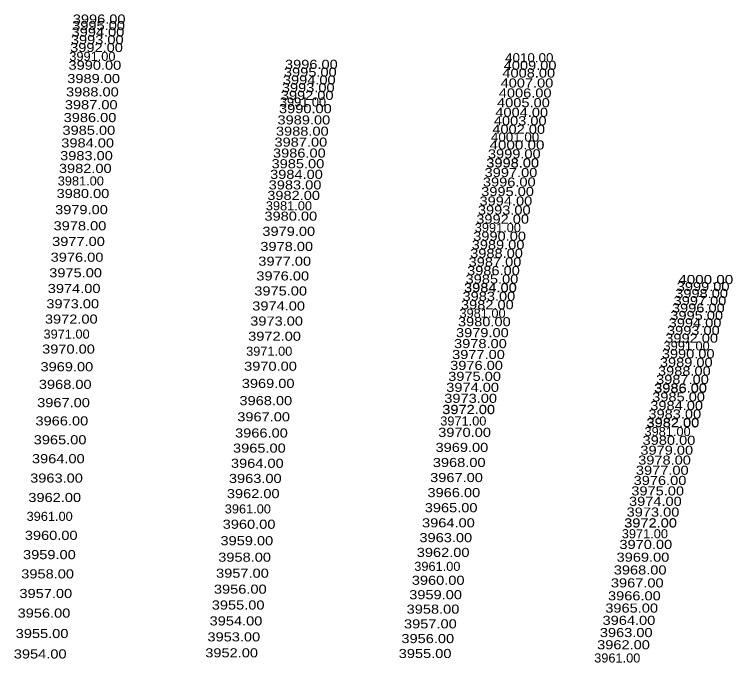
# Model space of a CAD drawing. Extents: x 49942 to 56479, y 47140 to 53283.
# Drawn here: x 54100.5 to 54495.6, y 49903.4 to 50259.9 of the extents above; entities that cross this region are included whole.
import ezdxf

# ---------------------------------------------------------------- set-up
doc = ezdxf.new("R2010")
doc.units = 0
doc.header["$LTSCALE"] = 2
doc.layers.add('29', color=7, linetype='Continuous')

msp = doc.modelspace()

# ---------------------------------------------------------------- texts
at = {"layer": '29'}
for s, width, p in [('3996.00', 1.2, (54132.674, 50254.795)), ('3995.00', 1.2, (54132.343, 50251.232)), ('3994.00', 1.2, (54132.012, 50247.668)), ('3993.00', 1.2, (54131.616, 50243.411)), ('3992.00', 1.2, (54131.22, 50239.153)), ('3991.00', 1.05, (54130.768, 50234.287)), ('4010.00', 1.1, (54370.453, 50233.532)), ('3990.00', 1.2, (54130.316, 50229.421)), ('3996.00', 1.2, (54249.399, 50229.894)), ('4009.00', 1.2, (54369.703, 50229.332)), ('3995.00', 1.2, (54248.818, 50225.606)), ('4008.00', 1.2, (54368.953, 50225.133)), ('3989.00', 1.2, (54129.634, 50222.087)), ('3994.00', 1.2, (54248.237, 50221.318)), ('3993.00', 1.2, (54247.663, 50217.082)), ('4007.00', 1.2, (54367.972, 50219.641)), ('3988.00', 1.2, (54128.953, 50214.753)), ('3992.00', 1.2, (54247.089, 50212.847)), ('4006.00', 1.2, (54366.991, 50214.148)), ('3991.00', 1.05, (54246.594, 50209.192)), ('4005.00', 1.2, (54366.041, 50208.829)), ('3987.00', 1.2, (54128.297, 50207.696)), ('3990.00', 1.2, (54246.098, 50205.537)), ('3986.00', 1.2, (54127.641, 50200.639)), ('4004.00', 1.2, (54365.092, 50203.51)), ('3989.00', 1.2, (54245.259, 50199.343)), ('4003.00', 1.2, (54364.26, 50198.855)), ('3985.00', 1.2, (54126.992, 50193.66)), ('3988.00', 1.2, (54244.419, 50193.149)), ('4002.00', 1.2, (54363.429, 50194.2)), ('4001.00', 1.1, (54362.659, 50189.891)), ('3984.00', 1.2, (54126.343, 50186.681)), ('3987.00', 1.2, (54243.604, 50187.132)), ('4000.00', 1.25, (54361.889, 50185.581)), ('3986.00', 1.2, (54242.789, 50181.116)), ('3983.00', 1.2, (54125.693, 50179.681)), ('3999.00', 1.2, (54361.014, 50180.682)), ('3985.00', 1.2, (54241.995, 50175.258)), ('3998.00', 1.2, (54360.113, 50175.635)), ('3998.00', 1.2, (54360.125, 50175.702)), ('3998.00', 1.2, (54360.137, 50175.77)), ('3982.00', 1.2, (54125.042, 50172.678)), ('3984.00', 1.2, (54241.201, 50169.4)), ('3997.00', 1.2, (54359.181, 50170.417)), ('3981.00', 1.05, (54124.401, 50165.776)), ('3996.00', 1.2, (54358.249, 50165.2)), ('3983.00', 1.2, (54240.416, 50163.614)), ('3980.00', 1.2, (54123.759, 50158.875)), ('3982.00', 1.2, (54239.632, 50157.828)), ('3995.00', 1.2, (54357.316, 50159.973)), ('3994.00', 1.2, (54356.382, 50154.746)), ('3979.00', 1.2, (54122.934, 50149.999)), ('3981.00', 1.05, (54238.86, 50152.126)), ('3993.00', 1.2, (54355.495, 50149.781)), ('3980.00', 1.2, (54238.087, 50146.424)), ('3992.00', 1.2, (54354.609, 50144.816)), ('3978.00', 1.2, (54122.109, 50141.123)), ('3979.00', 1.2, (54236.957, 50138.092)), ('3991.00', 1.05, (54353.768, 50140.109)), ('3990.00', 1.2, (54352.927, 50135.402)), ('3977.00', 1.2, (54121.309, 50132.512)), ('3978.00', 1.2, (54235.828, 50129.759)), ('3989.00', 1.2, (54352.086, 50130.694)), ('3988.00', 1.2, (54351.245, 50125.985)), ('3976.00', 1.2, (54120.504, 50123.85)), ('3977.00', 1.2, (54234.731, 50121.662)), ('3987.00', 1.2, (54350.397, 50121.237)), ('3975.00', 1.2, (54119.708, 50115.283)), ('3986.00', 1.2, (54349.549, 50116.489)), ('3976.00', 1.2, (54233.633, 50113.565)), ('3985.00', 1.2, (54348.719, 50111.843)), ('4000.00', 1.25, (54465.722, 50111.562)), ('3974.00', 1.2, (54118.906, 50106.654)), ('3984.00', 1.2, (54347.858, 50107.022)), ('3984.00', 1.2, (54347.875, 50107.116)), ('3984.00', 1.2, (54347.89, 50107.197)), ('3999.00', 1.2, (54464.874, 50107.75)), ('3975.00', 1.2, (54232.514, 50105.309)), ('3983.00', 1.2, (54347.026, 50102.362)), ('3998.00', 1.2, (54464.026, 50103.938)), ('3973.00', 1.2, (54118.124, 50098.238)), ('3997.00', 1.2, (54463.136, 50099.931)), ('3974.00', 1.2, (54231.396, 50097.053)), ('3982.00', 1.2, (54346.194, 50097.702)), ('3996.00', 1.2, (54462.245, 50095.925)), ('3981.00', 1.05, (54345.361, 50093.038)), ('3995.00', 1.2, (54461.34, 50091.856)), ('3972.00', 1.2, (54117.342, 50089.823)), ('3973.00', 1.2, (54230.269, 50088.741)), ('3980.00', 1.2, (54344.528, 50088.374)), ('3994.00', 1.2, (54460.435, 50087.786)), ('3979.00', 1.2, (54343.455, 50082.368)), ('3993.00', 1.2, (54459.501, 50083.582)), ('3971.00', 1.05, (54116.575, 50081.58)), ('3972.00', 1.2, (54229.14, 50080.412)), ('3992.00', 1.2, (54458.566, 50079.377)), ('3978.00', 1.2, (54342.382, 50076.361)), ('3991.00', 1.05, (54457.608, 50075.069)), ('3970.00', 1.2, (54115.809, 50073.337)), ('3971.00', 1.05, (54228.023, 50072.165)), ('3977.00', 1.2, (54341.311, 50070.363)), ('3990.00', 1.2, (54456.65, 50070.761)), ('3969.00', 1.2, (54114.907, 50063.632)), ('3970.00', 1.2, (54226.905, 50063.919)), ('3976.00', 1.2, (54340.24, 50064.365)), ('3989.00', 1.2, (54455.597, 50066.022)), ('3975.00', 1.2, (54339.162, 50058.334)), ('3988.00', 1.2, (54454.543, 50061.283)), ('3969.00', 1.2, (54225.622, 50054.451)), ('3987.00', 1.2, (54453.512, 50056.646)), ('3968.00', 1.2, (54114.005, 50053.927)), ('3974.00', 1.2, (54338.085, 50052.303)), ('3986.00', 1.2, (54452.433, 50051.795)), ('3986.00', 1.2, (54452.458, 50051.904)), ('3986.00', 1.2, (54452.481, 50052.009)), ('3985.00', 1.2, (54451.376, 50047.037)), ('3967.00', 1.2, (54113.072, 50043.888)), ('3968.00', 1.2, (54224.339, 50044.984)), ('3973.00', 1.2, (54337.004, 50046.249)), ('3972.00', 1.2, (54335.899, 50040.064)), ('3972.00', 1.2, (54335.912, 50040.137)), ('3972.00', 1.2, (54335.923, 50040.196)), ('3984.00', 1.2, (54450.318, 50042.28)), ('3967.00', 1.2, (54223.134, 50036.096)), ('3983.00', 1.2, (54449.286, 50037.636)), ('3966.00', 1.2, (54112.139, 50033.849)), ('3971.00', 1.05, (54334.781, 50033.802)), ('3982.00', 1.2, (54448.201, 50032.758)), ('3982.00', 1.2, (54448.227, 50032.877)), ('3982.00', 1.2, (54448.253, 50032.992)), ('3966.00', 1.2, (54221.93, 50027.208)), ('3970.00', 1.2, (54333.663, 50027.541)), ('3981.00', 1.05, (54447.136, 50027.97)), ('3965.00', 1.2, (54111.174, 50023.461)), ('3980.00', 1.2, (54446.072, 50023.181)), ('3965.00', 1.2, (54220.8, 50018.871)), ('3969.00', 1.2, (54332.183, 50019.258)), ('3979.00', 1.2, (54444.861, 50017.735)), ('3964.00', 1.2, (54110.208, 50013.073)), ('3968.00', 1.2, (54330.704, 50010.975)), ('3978.00', 1.2, (54443.65, 50012.289)), ('3964.00', 1.2, (54219.67, 50010.533)), ('3977.00', 1.2, (54442.406, 50006.695)), ('3963.00', 1.2, (54109.217, 50002.404)), ('3963.00', 1.2, (54218.54, 50002.201)), ('3967.00', 1.2, (54329.226, 50002.703)), ('3976.00', 1.2, (54441.163, 50001.101)), ('3975.00', 1.2, (54439.886, 49995.358)), ('3962.00', 1.2, (54108.225, 49991.735)), ('3962.00', 1.2, (54217.411, 49993.87)), ('3966.00', 1.2, (54327.749, 49994.43)), ('3974.00', 1.2, (54438.609, 49989.615)), ('3961.00', 1.05, (54216.271, 49985.452)), ('3965.00', 1.2, (54326.264, 49986.117)), ('3973.00', 1.2, (54437.298, 49983.719)), ('3961.00', 1.05, (54107.261, 49981.363)), ('3960.00', 1.2, (54215.13, 49977.034)), ('3964.00', 1.2, (54324.779, 49977.804)), ('3972.00', 1.2, (54435.958, 49977.694)), ('3972.00', 1.2, (54435.973, 49977.758)), ('3972.00', 1.2, (54435.987, 49977.822)), ('3971.00', 1.05, (54434.649, 49971.803)), ('3960.00', 1.2, (54106.289, 49970.906)), ('3959.00', 1.2, (54213.901, 49967.968)), ('3963.00', 1.2, (54323.326, 49969.666)), ('3970.00', 1.2, (54433.339, 49965.912)), ('3959.00', 1.2, (54105.305, 49960.319)), ('3962.00', 1.2, (54321.872, 49961.528)), ('3958.00', 1.2, (54212.672, 49958.901)), ('3969.00', 1.2, (54431.781, 49958.903)), ('3961.00', 1.05, (54320.505, 49953.872)), ('3968.00', 1.2, (54430.222, 49951.894)), ('3958.00', 1.2, (54104.321, 49949.731)), ('3957.00', 1.2, (54211.481, 49950.113)), ('3960.00', 1.2, (54319.138, 49946.216)), ('3967.00', 1.2, (54428.641, 49944.782)), ('3956.00', 1.2, (54210.29, 49941.324)), ('3957.00', 1.2, (54103.319, 49938.951)), ('3959.00', 1.2, (54317.719, 49938.276)), ('3966.00', 1.2, (54427.06, 49937.671)), ('3955.00', 1.2, (54209.11, 49932.617)), ('3956.00', 1.2, (54102.317, 49928.171)), ('3958.00', 1.2, (54316.302, 49930.337)), ('3965.00', 1.2, (54425.562, 49930.934)), ('3964.00', 1.2, (54424.064, 49924.196)), ('3954.00', 1.2, (54207.925, 49923.874)), ('3957.00', 1.2, (54314.857, 49922.252)), ('3955.00', 1.2, (54101.274, 49916.941)), ('3963.00', 1.2, (54422.569, 49917.473)), ('3953.00', 1.2, (54206.736, 49915.098)), ('3956.00', 1.2, (54313.413, 49914.167)), ('3962.00', 1.2, (54421.075, 49910.751)), ('3954.00', 1.2, (54100.23, 49905.711)), ('3952.00', 1.2, (54205.546, 49906.322)), ('3955.00', 1.2, (54311.946, 49905.951)), ('3961.00', 1.05, (54419.462, 49903.498))]:
    msp.add_text(s, height=5, dxfattribs=dict(at, width=width)).set_placement(p)

doc.saveas('drawing.dxf')
